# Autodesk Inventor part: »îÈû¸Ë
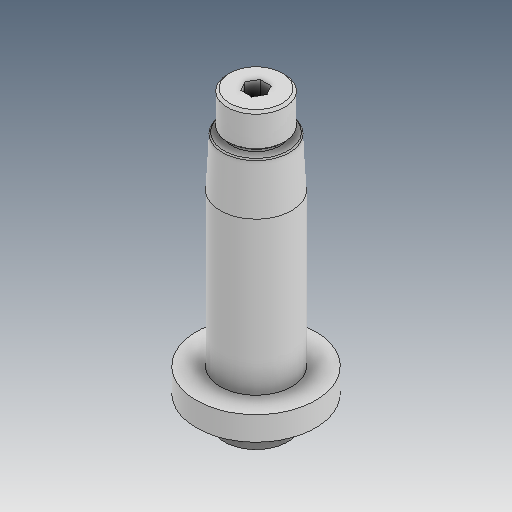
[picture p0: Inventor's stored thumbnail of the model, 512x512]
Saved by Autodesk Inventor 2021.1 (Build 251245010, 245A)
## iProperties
Created: 2019-04
Part Number: »îÈû¸Ë
Material: Ogólny
Document SubType Name: Modeling
Designer: user
Density: 1 g/cm^3
Appearance: Domyślna
Author: user
Revision Number: ÈÎºÎ
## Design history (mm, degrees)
feature "ÇÐ³ý-À­Éì1"
node "Bryła1"
